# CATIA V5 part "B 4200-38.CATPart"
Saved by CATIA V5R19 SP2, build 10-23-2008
Part number: B 4200-38
Bounding box of the stored display mesh (mm): x -47.487 to 47.487, y -47.487 to 47.487, z 0 to 196
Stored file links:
  C:\Users\Bora\Desktop\3D Katı model\B serisi\B 4200\B 4200-38.CATPart
  C:\Program Files\Dassault Systemes\B19\intel_a\reffiles\standard\MetricThickPitch.txt
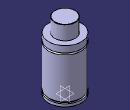
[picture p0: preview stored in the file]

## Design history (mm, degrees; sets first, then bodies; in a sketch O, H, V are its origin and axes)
Body1 (main body)
  Sketch1 on yz-plane, origin (0, 0, 0), H (0, 1, 0), V (0, 0, 1)
    point P1 (47.5, 136.5)
    point P2 (47.5, 131.5)
    point P3 (47.5, 136.5)
    point P6 (47.5, 131.5)
    point P9 (30, 195)
    point P11 (30, 195)
    arc A1 centre (47.5, 134) radius 2.5 from (47.5, 136.5) to (47.5, 131.5) ccw
    line L1 (47.5, 136.5) -> (47.5, 155)
    line L2 (47.5, 13) -> (47.5, 131.5)
    line L3 (43.5, 13) -> (43.5, 8)
    arc A2 centre (29, 195) radius 1 from (30, 195) to (29, 196) ccw
    line L4 (30, 195) -> (30, 155)
    line L5 (47.5, 0) -> (47.5, 8)
    line L6 (29, 196) -> (0, 196)
    point P15 (0, 196)
    line L7 (30, 155) -> (47.5, 155)
    line L8 (0, 0) -> (47.5, 0)
    line L9 (43.5, 8) -> (47.5, 8)
    line L10 (43.5, 13) -> (47.5, 13)
    coincidence: P15 V, P1 P3, P2 P6, P9 P11
    tangency: L6 A2
    horizontal: L7 H, L8 H, L9 H, L10 H
  Shaft1: profile Sketch1, axis Sketch1.V, angle 360
  Sketch2 on face of Shaft1 from Sketch1.L8, origin (0, 0, 0), H (1, 0, 0), V (0, -1, 0)
    point P1 (30, 0)
    distance P1 V = 30
  Hole1: placed by Sketch2, at (30, 0, 0) direction (0, 0, 1), diameter 6.647, depth 13, threaded "M8", thread diameter 8, thread depth 13, pitch 1.25
  CircPattern1: of Hole1, instances 4, angular step 90, axis from xy-plane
